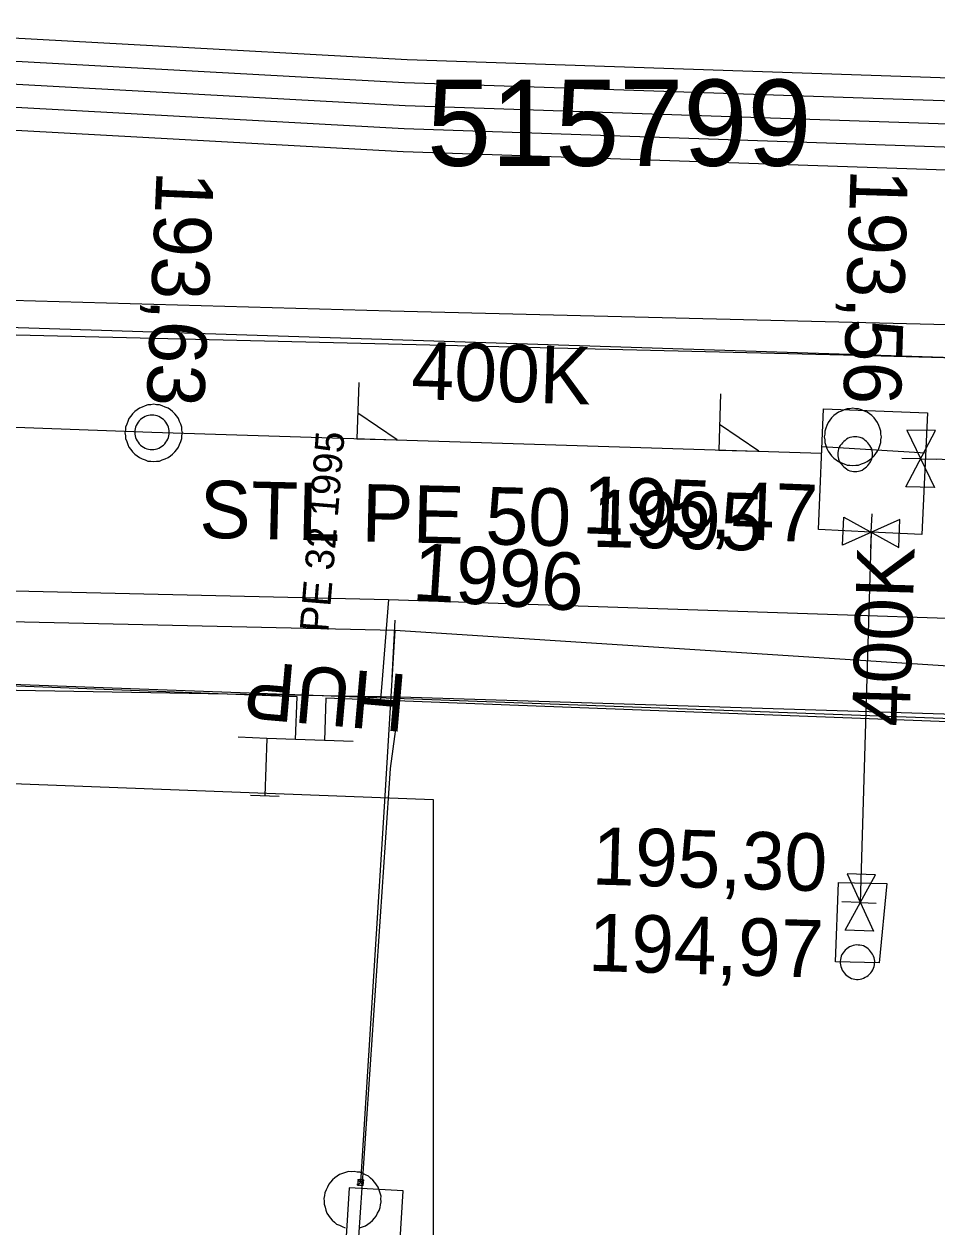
# Model space of a CAD drawing. Extents: x -746464 to -745690, y -1051581 to -1049993.
# Drawn here: x -746101.53 to -746085.64, y -1051042.46 to -1051021.54 of the extents above; entities that cross this region are included whole.
import ezdxf

# ---------------------------------------------------------------- set-up
doc = ezdxf.new("R2010")
doc.units = 0
for name, color, linetype in [('04_CETIN_NN', 7, 'Continuous'), ('04_CETIN_sdelovaci_podzem', 7, 'Continuous'), ('37_TVNET_sdelovaci_televizni kabely', 7, 'Continuous'), ('45_Eltodo_popisy', 7, 'Continuous'), ('45_Eltodo_sdelovaci_kabel_ovladaci', 7, 'Continuous'), ('45_Eltodo_vedeni_NN_zemni', 7, 'Continuous'), ('48_Prazs_plynarenska_STL', 7, 'Continuous'), ('48_Prazs_plynarenska_STL_popisy', 7, 'Continuous'), ('51_PVaK_kanal_jednotna_overena poloha_rad', 7, 'Continuous'), ('51_PVaK_kanal_NEPROVOZUJE PVK_overena poloha', 7, 'Continuous'), ('51_PVaK_kanal_objekty', 7, 'Continuous'), ('51_PVaK_kanal_popisy', 7, 'Continuous'), ('51_PVaK_kanal_zruseno_overena poloha', 7, 'Continuous'), ('51_PVaK_vodovod_chranicky_objekty', 7, 'Continuous'), ('51_PVaK_vodovod_overena poloha_pripojka', 7, 'Continuous'), ('51_PVaK_vodovod_overena poloha_rad', 7, 'Continuous'), ('51_PVaK_vodovod_popisy', 7, 'Continuous'), ('55_PREdi_NN', 7, 'Continuous'), ('55_PREdi_NN_pripojovaci_misto', 7, 'Continuous')]:
    doc.layers.add(name, color=color, linetype=linetype)

msp = doc.modelspace()

# ---------------------------------------------------------------- linework, layer by layer
at = {"layer": '04_CETIN_NN'}
msp.add_lwpolyline([(-746057.75, -1051028.08), (-746087.26, -1051027.3), (-746131.43, -1051026.23), (-746132.58, -1051026.03), (-746137.16, -1051023.83), (-746146.04, -1051015.8), (-746146.14, -1051015.34)], dxfattribs=at)
at = {"layer": '04_CETIN_sdelovaci_podzem'}
for points in [[(-746057.75, -1051028.08), (-746087.26, -1051027.3), (-746131.43, -1051026.23), (-746132.58, -1051026.03), (-746137.16, -1051023.83), (-746146.04, -1051015.8), (-746146.14, -1051015.34)], [(-746051.11, -1051027.62), (-746084.98, -1051026.78), (-746095.15, -1051026.53), (-746111.63, -1051026.07), (-746132.51, -1051025.74)], [(-746094.98, -1051033.25), (-746112.02, -1051032.95)], [(-746100.82, -1051048.45), (-746100.68, -1051043.04), (-746095.76, -1051043.5), (-746095.15, -1051034.49), (-746094.98, -1051033.25)], [(-746050.85, -1051034.63), (-746084.03, -1051033.59), (-746094.98, -1051033.25)], [(-746095.76, -1051043.5), (-746095.15, -1051034.49)]]:
    msp.add_lwpolyline(points, dxfattribs=at)
at = {"layer": '37_TVNET_sdelovaci_televizni kabely'}
for points in [[(-745984.595, -1050626.363), (-746079.15, -1050602.616), (-746117.902, -1050728.62), (-746140.499, -1050964.785), (-746150.343, -1051014.385), (-746134.374, -1051025.766), (-746053.56, -1051028.358)], [(-746164.092, -1051025.501), (-746164.092, -1051032.378), (-746094.407, -1051035.026)], [(-746094.407, -1051035.026), (-746094.407, -1051053.691), (-746100.482, -1051053.691)]]:
    msp.add_lwpolyline(points, dxfattribs=at)
at = {"layer": '45_Eltodo_sdelovaci_kabel_ovladaci'}
for points in [[(-746165.45, -1051019.12), (-746164.645, -1051018.484), (-746163.012, -1051015.524), (-746155.55, -1051020.103), (-746128.916, -1051021.082), (-746094.892, -1051022.957), (-746062.41, -1051024.051), (-746028.782, -1051025.923), (-745993.864, -1051027.813), (-745962.878, -1051029.504), (-745938.694, -1051029.59), (-745937.853, -1051017.666)], [(-746165.45, -1051019.12), (-746164.312, -1051018.623), (-746162.86, -1051016.086), (-746155.668, -1051020.501), (-746128.943, -1051021.481), (-746094.909, -1051023.356), (-746062.428, -1051024.45), (-746028.804, -1051026.323), (-745993.885, -1051028.213), (-745962.902, -1051029.904), (-745931.905, -1051029.989), (-745932.65, -1051042.244), (-745896.705, -1051050.601), (-745888.091, -1051054.568), (-745887.715, -1051053.926), (-745888.006, -1051054.643), (-745887.529, -1051054.877), (-745867.231, -1051055.559), (-745868.29, -1051094.52)]]:
    msp.add_lwpolyline(points, dxfattribs=at)
at = {"layer": '45_Eltodo_vedeni_NN_zemni'}
for points in [[(-746165.45, -1051019.12), (-746165.385, -1051018.211), (-746163.315, -1051014.399), (-746155.315, -1051019.309), (-746128.86, -1051020.284), (-746094.856, -1051022.157), (-746062.375, -1051023.251), (-746028.738, -1051025.124), (-745993.82, -1051027.014), (-745962.83, -1051028.706), (-745954.147, -1051028.453), (-745931.268, -1051028.32), (-745933.203, -1051055.903)], [(-746165.45, -1051019.12), (-746164.568, -1051017.613), (-746163.161, -1051014.992), (-746155.446, -1051019.718), (-746128.935, -1051020.682), (-746094.904, -1051022.556), (-746062.441, -1051023.642), (-746028.749, -1051025.516), (-745993.88, -1051027.407), (-745962.99, -1051029.049), (-745953.059, -1051029.043), (-745952.784, -1051028.189)], [(-746128.971, -1051021.88), (-746094.927, -1051023.756)], [(-746094.927, -1051023.756), (-746062.446, -1051024.85)]]:
    msp.add_lwpolyline(points, dxfattribs=at)
at = {"layer": '48_Prazs_plynarenska_STL'}
for points in [[(-746142.85, -1051030.58), (-746140.03, -1051030.48), (-746112.47, -1051031.15), (-746095.18, -1051031.55), (-746077.47, -1051032.14), (-746054.623, -1051033.192)], [(-746095.18, -1051031.55), (-746095.288, -1051032.862)], [(-746095.288, -1051032.862), (-746095.329, -1051033.359)]]:
    msp.add_lwpolyline(points, dxfattribs=at)
at = {"layer": '51_PVaK_kanal_jednotna_overena poloha_rad'}
for p, q in [((-746135.666, -1051027.315), (-746099.3, -1051028.64)), ((-746099.3, -1051028.64), (-746087.643, -1051029.004)), ((-746085.92, -1051029.1), (-746050.875, -1051029.746))]:
    msp.add_line(p, q, dxfattribs=at)
at = {"layer": '51_PVaK_kanal_NEPROVOZUJE PVK_overena poloha'}
msp.add_line((-746086.78, -1051030.38), (-746086.97, -1051036.82), dxfattribs=at)
at = {"layer": '51_PVaK_kanal_objekty'}
for p, q in [((-746086.176, -1051029.591), (-746085.664, -1051028.609)), ((-746085.664, -1051028.609), (-746086.159, -1051028.6)), ((-746086.159, -1051028.6), (-746085.681, -1051029.6)), ((-746085.92, -1051029.1), (-746086.247, -1051029.094)), ((-746085.92, -1051029.1), (-746085.642, -1051029.105)), ((-746085.681, -1051029.6), (-746086.176, -1051029.591)), ((-746087.28, -1051030.604), (-746087.259, -1051030.115)), ((-746086.28, -1051030.156), (-746087.28, -1051030.604)), ((-746087.259, -1051030.115), (-746086.301, -1051030.645)), ((-746086.78, -1051030.38), (-746086.766, -1051030.057)), ((-746086.301, -1051030.645), (-746086.28, -1051030.156)), ((-746086.78, -1051030.38), (-746086.791, -1051030.654)), ((-746086.706, -1051036.339), (-746087.197, -1051036.32)), ((-746087.197, -1051036.32), (-746086.743, -1051037.32)), ((-746087.234, -1051037.301), (-746086.706, -1051036.339)), ((-746086.97, -1051036.82), (-746087.294, -1051036.808)), ((-746086.97, -1051036.82), (-746086.695, -1051036.831)), ((-746086.743, -1051037.32), (-746087.234, -1051037.301))]:
    msp.add_line(p, q, dxfattribs=at)
for points in [[(-746095.701, -1051027.773), (-746095.732, -1051028.751), (-746095.034, -1051028.773), (-746095.718, -1051028.31)], [(-746098.77, -1051028.65), (-746098.78, -1051028.6), (-746098.78, -1051028.55), (-746098.8, -1051028.5), (-746098.82, -1051028.45), (-746098.84, -1051028.4), (-746098.87, -1051028.36), (-746098.9, -1051028.32), (-746098.94, -1051028.28), (-746098.98, -1051028.25), (-746099.02, -1051028.22), (-746099.07, -1051028.2), (-746099.12, -1051028.18), (-746099.17, -1051028.16), (-746099.22, -1051028.16), (-746099.27, -1051028.15), (-746099.32, -1051028.16), (-746099.37, -1051028.16), (-746099.42, -1051028.18), (-746099.47, -1051028.2), (-746099.52, -1051028.22), (-746099.56, -1051028.25), (-746099.6, -1051028.28), (-746099.64, -1051028.32), (-746099.67, -1051028.36), (-746099.7, -1051028.4), (-746099.72, -1051028.45), (-746099.74, -1051028.5), (-746099.76, -1051028.55), (-746099.76, -1051028.6), (-746099.77, -1051028.65), (-746099.76, -1051028.7), (-746099.76, -1051028.75), (-746099.74, -1051028.8), (-746099.72, -1051028.85), (-746099.7, -1051028.9), (-746099.67, -1051028.94), (-746099.64, -1051028.98), (-746099.6, -1051029.02), (-746099.56, -1051029.05), (-746099.52, -1051029.08), (-746099.47, -1051029.1), (-746099.42, -1051029.12), (-746099.37, -1051029.14), (-746099.32, -1051029.14), (-746099.27, -1051029.15), (-746099.22, -1051029.14), (-746099.17, -1051029.14), (-746099.12, -1051029.12), (-746099.07, -1051029.1), (-746099.02, -1051029.08), (-746098.98, -1051029.05), (-746098.94, -1051029.02), (-746098.9, -1051028.98), (-746098.87, -1051028.94), (-746098.84, -1051028.9), (-746098.82, -1051028.85), (-746098.8, -1051028.8), (-746098.78, -1051028.75), (-746098.78, -1051028.7), (-746098.77, -1051028.65)], [(-746089.404, -1051027.97), (-746089.435, -1051028.948), (-746088.737, -1051028.97), (-746089.421, -1051028.507)], [(-746099, -1051028.64), (-746099, -1051028.61), (-746099.006, -1051028.58), (-746099.012, -1051028.55), (-746099.024, -1051028.52), (-746099.042, -1051028.49), (-746099.06, -1051028.466), (-746099.078, -1051028.442), (-746099.102, -1051028.418), (-746099.126, -1051028.4), (-746099.15, -1051028.382), (-746099.18, -1051028.364), (-746099.21, -1051028.352), (-746099.24, -1051028.346), (-746099.27, -1051028.34), (-746099.3, -1051028.34), (-746099.33, -1051028.34), (-746099.36, -1051028.346), (-746099.39, -1051028.352), (-746099.42, -1051028.364), (-746099.45, -1051028.382), (-746099.474, -1051028.4), (-746099.498, -1051028.418), (-746099.522, -1051028.442), (-746099.54, -1051028.466), (-746099.558, -1051028.49), (-746099.576, -1051028.52), (-746099.588, -1051028.55), (-746099.594, -1051028.58), (-746099.6, -1051028.61), (-746099.6, -1051028.64), (-746099.6, -1051028.67), (-746099.594, -1051028.7), (-746099.588, -1051028.73), (-746099.576, -1051028.76), (-746099.558, -1051028.79), (-746099.54, -1051028.814), (-746099.522, -1051028.838), (-746099.498, -1051028.862), (-746099.474, -1051028.88), (-746099.45, -1051028.898), (-746099.42, -1051028.916), (-746099.39, -1051028.928), (-746099.36, -1051028.934), (-746099.33, -1051028.94), (-746099.3, -1051028.94), (-746099.27, -1051028.94), (-746099.24, -1051028.934), (-746099.21, -1051028.928), (-746099.18, -1051028.916), (-746099.15, -1051028.898), (-746099.126, -1051028.88), (-746099.102, -1051028.862), (-746099.078, -1051028.838), (-746099.06, -1051028.814), (-746099.042, -1051028.79), (-746099.024, -1051028.76), (-746099.012, -1051028.73), (-746099.006, -1051028.7), (-746099, -1051028.67), (-746099, -1051028.64)], [(-746086.6, -1051028.72), (-746086.61, -1051028.67), (-746086.61, -1051028.62), (-746086.63, -1051028.57), (-746086.65, -1051028.52), (-746086.67, -1051028.47), (-746086.7, -1051028.43), (-746086.73, -1051028.39), (-746086.77, -1051028.35), (-746086.81, -1051028.32), (-746086.85, -1051028.29), (-746086.9, -1051028.27), (-746086.95, -1051028.25), (-746087, -1051028.23), (-746087.05, -1051028.23), (-746087.1, -1051028.22), (-746087.15, -1051028.23), (-746087.2, -1051028.23), (-746087.25, -1051028.25), (-746087.3, -1051028.27), (-746087.35, -1051028.29), (-746087.39, -1051028.32), (-746087.43, -1051028.35), (-746087.47, -1051028.39), (-746087.5, -1051028.43), (-746087.53, -1051028.47), (-746087.55, -1051028.52), (-746087.57, -1051028.57), (-746087.59, -1051028.62), (-746087.59, -1051028.67), (-746087.6, -1051028.72), (-746087.59, -1051028.77), (-746087.59, -1051028.82), (-746087.57, -1051028.87), (-746087.55, -1051028.92), (-746087.53, -1051028.97), (-746087.5, -1051029.01), (-746087.47, -1051029.05), (-746087.43, -1051029.09), (-746087.39, -1051029.12), (-746087.35, -1051029.15), (-746087.3, -1051029.17), (-746087.25, -1051029.19), (-746087.2, -1051029.21), (-746087.15, -1051029.21), (-746087.1, -1051029.22), (-746087.05, -1051029.21), (-746087, -1051029.21), (-746086.95, -1051029.19), (-746086.9, -1051029.17), (-746086.85, -1051029.15), (-746086.81, -1051029.12), (-746086.77, -1051029.09), (-746086.73, -1051029.05), (-746086.7, -1051029.01), (-746086.67, -1051028.97), (-746086.65, -1051028.92), (-746086.63, -1051028.87), (-746086.61, -1051028.82), (-746086.61, -1051028.77), (-746086.6, -1051028.72)], [(-746086.76, -1051029.02), (-746086.76, -1051028.99), (-746086.766, -1051028.96), (-746086.772, -1051028.93), (-746086.784, -1051028.9), (-746086.802, -1051028.87), (-746086.82, -1051028.846), (-746086.838, -1051028.822), (-746086.862, -1051028.798), (-746086.886, -1051028.78), (-746086.91, -1051028.762), (-746086.94, -1051028.744), (-746086.97, -1051028.732), (-746087, -1051028.726), (-746087.03, -1051028.72), (-746087.06, -1051028.72), (-746087.09, -1051028.72), (-746087.12, -1051028.726), (-746087.15, -1051028.732), (-746087.18, -1051028.744), (-746087.21, -1051028.762), (-746087.234, -1051028.78), (-746087.258, -1051028.798), (-746087.282, -1051028.822), (-746087.3, -1051028.846), (-746087.318, -1051028.87), (-746087.336, -1051028.9), (-746087.348, -1051028.93), (-746087.354, -1051028.96), (-746087.36, -1051028.99), (-746087.36, -1051029.02), (-746087.36, -1051029.05), (-746087.354, -1051029.08), (-746087.348, -1051029.11), (-746087.336, -1051029.14), (-746087.318, -1051029.17), (-746087.3, -1051029.194), (-746087.282, -1051029.218), (-746087.258, -1051029.242), (-746087.234, -1051029.26), (-746087.21, -1051029.278), (-746087.18, -1051029.296), (-746087.15, -1051029.308), (-746087.12, -1051029.314), (-746087.09, -1051029.32), (-746087.06, -1051029.32), (-746087.03, -1051029.32), (-746087, -1051029.314), (-746086.97, -1051029.308), (-746086.94, -1051029.296), (-746086.91, -1051029.278), (-746086.886, -1051029.26), (-746086.862, -1051029.242), (-746086.838, -1051029.218), (-746086.82, -1051029.194), (-746086.802, -1051029.17), (-746086.784, -1051029.14), (-746086.772, -1051029.11), (-746086.766, -1051029.08), (-746086.76, -1051029.05), (-746086.76, -1051029.02)], [(-746087.034, -1051038.156), (-746087.005, -1051038.157), (-746086.974, -1051038.153), (-746086.944, -1051038.148), (-746086.914, -1051038.138), (-746086.883, -1051038.121), (-746086.858, -1051038.104), (-746086.834, -1051038.088), (-746086.809, -1051038.065), (-746086.789, -1051038.042), (-746086.77, -1051038.019), (-746086.751, -1051037.99), (-746086.738, -1051037.96), (-746086.73, -1051037.931), (-746086.723, -1051037.901), (-746086.721, -1051037.871), (-746086.72, -1051037.842), (-746086.725, -1051037.811), (-746086.729, -1051037.781), (-746086.74, -1051037.751), (-746086.756, -1051037.72), (-746086.773, -1051037.695), (-746086.79, -1051037.671), (-746086.812, -1051037.646), (-746086.835, -1051037.627), (-746086.858, -1051037.608), (-746086.887, -1051037.588), (-746086.917, -1051037.575), (-746086.946, -1051037.567), (-746086.976, -1051037.56), (-746087.006, -1051037.559), (-746087.035, -1051037.557), (-746087.066, -1051037.562), (-746087.096, -1051037.566), (-746087.126, -1051037.577), (-746087.157, -1051037.593), (-746087.182, -1051037.61), (-746087.206, -1051037.627), (-746087.231, -1051037.649), (-746087.251, -1051037.672), (-746087.27, -1051037.695), (-746087.289, -1051037.724), (-746087.302, -1051037.754), (-746087.31, -1051037.783), (-746087.317, -1051037.813), (-746087.319, -1051037.843), (-746087.32, -1051037.873), (-746087.315, -1051037.903), (-746087.311, -1051037.933), (-746087.3, -1051037.963), (-746087.284, -1051037.994), (-746087.267, -1051038.019), (-746087.25, -1051038.043), (-746087.228, -1051038.069), (-746087.205, -1051038.088), (-746087.182, -1051038.107), (-746087.153, -1051038.126), (-746087.123, -1051038.139), (-746087.094, -1051038.147), (-746087.064, -1051038.154), (-746087.034, -1051038.156)]]:
    msp.add_lwpolyline(points, dxfattribs=at)
for points in [[(-746087.61, -1051028.23), (-746085.8, -1051028.3), (-746085.9, -1051030.42), (-746086.78, -1051030.38), (-746087.7, -1051030.33)], [(-746087.4, -1051037.85), (-746087.35, -1051036.47), (-746086.51, -1051036.49), (-746086.64, -1051037.87)]]:
    msp.add_lwpolyline(points, close=True, dxfattribs=at)
at = {"layer": '51_PVaK_kanal_zruseno_overena poloha'}
msp.add_line((-746087.638, -1051028.888), (-746085.833, -1051028.997), dxfattribs=at)
at = {"layer": '51_PVaK_vodovod_chranicky_objekty'}
for p, q in [((-746095.121, -1051032.91), (-746095.064, -1051031.91)), ((-746095.722, -1051041.735), (-746095.616, -1051041.641)), ((-746095.722, -1051041.735), (-746095.72, -1051041.715)), ((-746095.722, -1051041.735), (-746095.702, -1051041.736)), ((-746095.716, -1051041.635), (-746095.717, -1051041.655)), ((-746095.622, -1051041.741), (-746095.716, -1051041.635)), ((-746095.716, -1051041.635), (-746095.696, -1051041.636)), ((-746095.622, -1051041.741), (-746095.642, -1051041.74)), ((-746095.616, -1051041.641), (-746095.636, -1051041.64)), ((-746095.622, -1051041.741), (-746095.621, -1051041.721)), ((-746095.616, -1051041.641), (-746095.617, -1051041.661))]:
    msp.add_line(p, q, dxfattribs=at)
for points in [[(-746095.779, -1051041.497), (-746095.829, -1051041.504), (-746095.879, -1051041.501), (-746095.93, -1051041.518), (-746095.982, -1051041.535), (-746096.033, -1051041.552), (-746096.075, -1051041.579), (-746096.117, -1051041.607), (-746096.159, -1051041.644), (-746096.191, -1051041.682), (-746096.224, -1051041.721), (-746096.247, -1051041.769), (-746096.27, -1051041.818), (-746096.293, -1051041.867), (-746096.296, -1051041.917), (-746096.309, -1051041.966), (-746096.302, -1051042.017), (-746096.305, -1051042.067), (-746096.288, -1051042.118), (-746096.272, -1051042.169), (-746096.255, -1051042.221), (-746096.227, -1051042.262), (-746096.2, -1051042.304), (-746096.162, -1051042.347), (-746096.124, -1051042.379), (-746096.086, -1051042.412), (-746096.037, -1051042.435), (-746095.988, -1051042.458), (-746095.939, -1051042.481)], [(-746095.688, -1051042.476), (-746095.637, -1051042.459), (-746095.586, -1051042.442), (-746095.544, -1051042.415), (-746095.502, -1051042.387), (-746095.46, -1051042.35), (-746095.427, -1051042.311), (-746095.395, -1051042.273), (-746095.372, -1051042.225), (-746095.348, -1051042.176), (-746095.325, -1051042.127), (-746095.322, -1051042.077), (-746095.309, -1051042.028), (-746095.316, -1051041.977), (-746095.313, -1051041.927), (-746095.33, -1051041.876), (-746095.347, -1051041.825), (-746095.364, -1051041.773), (-746095.391, -1051041.731), (-746095.419, -1051041.69), (-746095.457, -1051041.647), (-746095.495, -1051041.615), (-746095.533, -1051041.582), (-746095.582, -1051041.559), (-746095.63, -1051041.536), (-746095.679, -1051041.513), (-746095.729, -1051041.51), (-746095.779, -1051041.497)], [(-746095.666, -1051041.638), (-746095.671, -1051041.638), (-746095.676, -1051041.638), (-746095.681, -1051041.639), (-746095.686, -1051041.641), (-746095.691, -1051041.643), (-746095.695, -1051041.646), (-746095.699, -1051041.649), (-746095.704, -1051041.653), (-746095.707, -1051041.657), (-746095.71, -1051041.66), (-746095.713, -1051041.665), (-746095.716, -1051041.67), (-746095.717, -1051041.675), (-746095.718, -1051041.68), (-746095.719, -1051041.685), (-746095.719, -1051041.69), (-746095.718, -1051041.695), (-746095.718, -1051041.7), (-746095.716, -1051041.705), (-746095.713, -1051041.71), (-746095.71, -1051041.714), (-746095.708, -1051041.719), (-746095.704, -1051041.723), (-746095.7, -1051041.726), (-746095.696, -1051041.729), (-746095.692, -1051041.733), (-746095.687, -1051041.735), (-746095.682, -1051041.736), (-746095.677, -1051041.738), (-746095.672, -1051041.738), (-746095.667, -1051041.738), (-746095.662, -1051041.737), (-746095.657, -1051041.737), (-746095.652, -1051041.735), (-746095.646, -1051041.732), (-746095.642, -1051041.73), (-746095.638, -1051041.727), (-746095.634, -1051041.723), (-746095.631, -1051041.719), (-746095.627, -1051041.716), (-746095.624, -1051041.711), (-746095.622, -1051041.706), (-746095.62, -1051041.701), (-746095.619, -1051041.696), (-746095.619, -1051041.691), (-746095.619, -1051041.686), (-746095.619, -1051041.681), (-746095.62, -1051041.676), (-746095.622, -1051041.671), (-746095.624, -1051041.666), (-746095.627, -1051041.661), (-746095.63, -1051041.657), (-746095.634, -1051041.653), (-746095.637, -1051041.65), (-746095.641, -1051041.647), (-746095.646, -1051041.643), (-746095.651, -1051041.641), (-746095.656, -1051041.64), (-746095.661, -1051041.638), (-746095.666, -1051041.638)]]:
    msp.add_lwpolyline(points, dxfattribs=at)
msp.add_lwpolyline([(-746094.984, -1051042.78), (-746094.927, -1051041.837), (-746095.869, -1051041.78), (-746095.927, -1051042.722)], close=True, dxfattribs=at)
at = {"layer": '51_PVaK_vodovod_overena poloha_pripojka'}
msp.add_line((-746095.07, -1051032.09), (-746095.09, -1051032.37), dxfattribs=at)
msp.add_lwpolyline([(-746095.09, -1051032.37), (-746095.261, -1051035.158), (-746095.668, -1051041.689)], dxfattribs=at)
at = {"layer": '51_PVaK_vodovod_overena poloha_rad'}
msp.add_lwpolyline([(-746077.51, -1051033.22), (-746095.07, -1051032.09), (-746112.36, -1051031.7), (-746140.08, -1051031.38), (-746159.77, -1051029.67)], dxfattribs=at)
at = {"layer": '55_PREdi_NN'}
for points in [[(-745933.351, -1051040.912), (-745941.504, -1051040.452), (-745958.538, -1051039.744), (-745969.12, -1051039.482), (-746015.2, -1051036.705), (-746033.432, -1051035.653), (-746045.186, -1051035.092), (-746119.381, -1051032.383), (-746168.04, -1051032.305), (-746181.2, -1051031.6)], [(-746096.799, -1051033.982), (-746096.772, -1051033.244), (-746113.255, -1051032.616), (-746113.286, -1051033.464)], [(-746045.651, -1051035.953), (-746045.623, -1051035.19), (-746096.272, -1051033.262), (-746096.299, -1051034)], [(-746095.799, -1051034.018), (-746096.299, -1051034), (-746096.799, -1051033.982), (-746097.299, -1051033.964), (-746097.798, -1051033.945)], [(-746097.299, -1051033.964), (-746097.317, -1051034.463)]]:
    msp.add_lwpolyline(points, dxfattribs=at)
at = {"layer": '55_PREdi_NN_pripojovaci_misto'}
for p, q in [((-746097.317, -1051034.463), (-746097.334, -1051034.963)), ((-746097.584, -1051034.954), (-746097.085, -1051034.971))]:
    msp.add_line(p, q, dxfattribs=at)

# ---------------------------------------------------------------- texts
at = {"layer": '45_Eltodo_popisy'}
msp.add_text('515799', height=1.5, dxfattribs=at).set_placement((-746094.513, -1051024.005))
at = {"layer": '48_Prazs_plynarenska_STL_popisy'}
for s, height, rotation, p in [('PE 32 1995', 0.5, 85.2942, (-746096.231, -1051032.127)), ('STL PE 50 1995', 1, 358.6747, (-746098.481, -1051030.473)), ('HUP', 1, 175, (-746094.829, -1051032.859))]:
    msp.add_text(s, height=height, rotation=rotation, dxfattribs=at).set_placement(p)
at = {"layer": '51_PVaK_kanal_popisy'}
for s, rotation, p in [('193,63', 267.545, (-746099.219, -1051024.082)), ('193,56', 268.2126, (-746087.138, -1051024.052)), ('400K', 358.2133, (-746094.794, -1051028.06)), ('195,47', 357.7863, (-746091.822, -1051030.395)), ('400K', 88.311, (-746086.116, -1051033.768)), ('195,30', 358.3103, (-746091.649, -1051036.505)), ('194,97', 358.3103, (-746091.715, -1051038.008))]:
    msp.add_text(s, height=1, rotation=rotation, dxfattribs=at).set_placement(p)
at = {"layer": '51_PVaK_vodovod_popisy'}
msp.add_text('1996', height=1, rotation=356.3177, dxfattribs=at).set_placement((-746094.782, -1051031.558))

doc.saveas('drawing.dxf')
